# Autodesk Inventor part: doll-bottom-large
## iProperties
Author: Administrator
Created: 2001-10
Part Number: doll-bottom-large
Document SubType Name: Modeling
Designer: Administrator
Control State: 0
Master: False
Checked Out: False
PropertySet Name: Design Tracking Control
Shininess: 64.0
Angle Display Precision: 2
Document Length Units: 11272
Document Angle Units: 11286
Document Time Units: 11279
Document Mass Units: 11290
Document Length Units Precision: 3
Document Angle Units Precision: 2
Compacted: True
PropertySet Name: _Private Model Information
Density: 0.0
Volumn: 0.0
Area: 0.0
PropertySet Name: Model Information
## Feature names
1. Derived Body1 [Tagging]
